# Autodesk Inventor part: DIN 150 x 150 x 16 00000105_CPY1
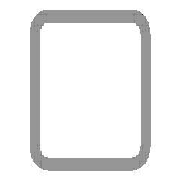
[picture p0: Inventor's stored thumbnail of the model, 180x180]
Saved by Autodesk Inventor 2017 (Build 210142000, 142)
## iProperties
Created: 2017-11
Part Number: DIN 150 x 150 x 16 00000105_CPY1
Material: Steel, Mild
Description: Cold formed welded structural hollow sections of non-alloy and fine grain structural steel
Document SubType Name: Modeling
Standard: DIN
Designer: iusti
Standard Revision: 2006-07
Standards Organization: DIN
Language: en-US
Size Designation: 150 x 150 x 16
Categories: <MemberInstance><Categories><Category DisplayName="Structural Shapes" InternalName="089c4875-fa83-4c05-b084-43b9cc11f5ed" Mnemonic="GRDR"><CategoryParameter Dis
Stock Number: 150 x 150 x 16
Mass: 90369.3 g
Surface Area: 14539.6 cm^2
Volume: 11512 cm^3
Density: 7.85 g/cm^3
Appearance: Semi-Polished
IsCustomPart: 1
G_W: 150.000 mm
G_H: 150.000 mm
G_L: 1539.608 mm
+DD82D223-1000-45B8-A0F4-80F9EFDCC45E+CUTDETAIL2: Cut
_CCFamilyMember: 76
_CCFamilyDisplayName: DIN EN 10219-2 (Square Hollow Section - Cold Formed) - Cold formed welded structural hollow sections of non-alloy and fine grain structural steel
_FrameMemberDoc: Frame Member File
_Version: 15.0.0
_GetPNFromCC: 1
Author: iusti
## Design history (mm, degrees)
node "Start plane"
node "End plane"
sketch "Sketch"
  geometry: L1 (-75, -27)-(-75, 27); L2 (-27, 75)-(27, 75); L3 (75, 27)-(75, -27); L4 (27, -75)-(-27, -75); L5 (-27, 59)-(27, 59); L6 (59, 27)-(59, -27); L7 (27, -59)-(-27, -59); L8 (-59, -27)-(-59, 27); L9 (0, 118.918)-(0, -118.918) reference; L10 (-118.918, 0)-(118.918, 0) reference; A1 r 48 centre (-27, -27) between (-75, -27) and (-27, -75); A2 r 48 centre (-27, 27) between (-27, 75) and (-75, 27); A3 r 48 centre (27, 27) between (75, 27) and (27, 75); A4 r 48 centre (27, -27) between (27, -75) and (75, -27); A5 r 32 centre (-27, 27) between (-27, 59) and (-59, 27); A6 r 32 centre (27, 27) between (59, 27) and (27, 59); A7 r 32 centre (27, -27) between (27, -59) and (59, -27); A8 r 32 centre (-27, -27) between (-59, -27) and (-27, -59)
  constraints: 16 end point, 16 point on circle, 8 centre point, 8 tangent, 4 parallel, 3 equal radius, 2 perpendicular, 7 other
  dimensions: "d7" = 48 radius of A1 (= G_IR); "d10" = 150 distance between parallel lines of L2 L4 (= G_H); "d11" = 150 distance between parallel lines of L1 L3 (= G_W); "d12" = 16 distance between parallel lines of L3 L6 (= G_T); "d15" = 75 distance between parallel lines of L2 L10 (= 0.5 x d10); "d16" = 75 distance between parallel lines of L9 L3 (= 0.5 x d11)
extrude "Body" new body sketch "Sketch" stored distance "d3" = 1539.60835 (= G_L); taper "d4" = 0 deg
node "Driven Length"
  sketch "Sketch3"
    geometry: L1 (0, 0)-(10, 0) reference
    constraints: 2 end point, 1 horizontal
  workplane "Work Plane3"
  sketch "Sketch4"
    geometry: L1 (-2, 75)-(12, 75) reference; L2 (-2, 1614.608)-(12, 1614.608) reference
    dimensions: "d18" = 1539.60835 distance between parallel lines of L1 L2 (derived)
workplane "Work Plane5"
split "Split2"
body "Solid1"
other parameters: "G_W" = 150 [user parameter; used in 1 equation term], "G_H" = 150 [user parameter; used in 1 equation term], "G_T" = 16 [user parameter; used in 1 equation term], "G_IR" = 48 [user parameter; used in 1 equation term], "G_L" = 1539.60835 (= d18) [user parameter; used in 1 equation term], "G_OFFSET_START" = -75 [user parameter; used in 1 equation term], "G_OFFSET_END" = 0 [user parameter; used in 1 equation term], "d13" = 75 (= -G_OFFSET_START), "d14" = 1614.60835 (= G_OFFSET_END + B_L), "B_L" = 1614.60835 [user parameter; used in 1 equation term], "d17" = 90 deg
